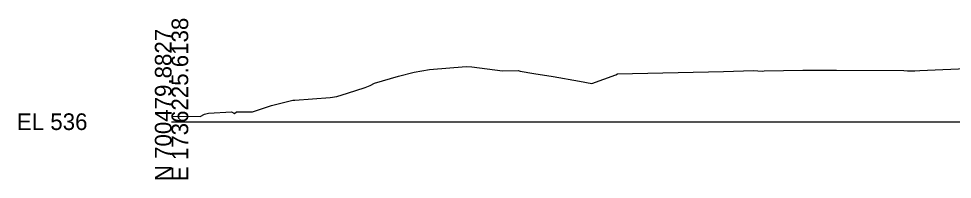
# Model space of a CAD drawing. Extents: x -26 to 803, y -10 to 646.
# Drawn here: x 474.3 to 631.2, y 190.3 to 217.3 of the extents above; entities that cross this region are included whole.
import ezdxf

# ---------------------------------------------------------------- set-up
doc = ezdxf.new("R2010")
doc.units = 0
for name, color, linetype in [('Default', 7, 'Continuous'), ('Exist Cross Section Cell', 7, 'Continuous'), ('Exist XS Ground Line', 7, 'Continuous')]:
    doc.layers.add(name, color=color, linetype=linetype)

msp = doc.modelspace()

# ---------------------------------------------------------------- linework, layer by layer
at = {"layer": 'Exist Cross Section Cell'}
msp.add_line((500, 200), (650, 200), dxfattribs=at)
at = {"layer": 'Exist XS Ground Line'}
for p, q in [((540.75, 208.33), (543.33, 208.78)), ((543.33, 208.78), (549.49, 209.28)), ((549.49, 209.28), (550.48, 209.2)), ((550.48, 209.2), (555.63, 208.56)), ((599.59, 208.53), (606.11, 208.69)), ((606.11, 208.69), (611.74, 208.64)), ((625.77, 208.61), (640.8, 209.23)), ((534.1, 206.47), (538.13, 207.66)), ((538.13, 207.66), (540.75, 208.33)), ((555.63, 208.56), (558.24, 208.58)), ((558.24, 208.58), (558.56, 208.49)), ((558.56, 208.49), (560.86, 208.09)), ((560.86, 208.09), (564.15, 207.62)), ((564.15, 207.62), (568.53, 206.82)), ((570.61, 206.42), (574.64, 207.89)), ((574.64, 207.89), (574.95, 208.03)), ((574.95, 208.03), (592.75, 208.41)), ((592.75, 208.41), (597.8, 208.59)), ((597.8, 208.59), (599.25, 208.52)), ((599.25, 208.52), (599.59, 208.53)), ((611.74, 208.64), (623.08, 208.62)), ((623.08, 208.62), (623.68, 208.55)), ((623.68, 208.55), (624.91, 208.54)), ((624.91, 208.54), (625.77, 208.61)), ((529.55, 204.8), (532.52, 205.74)), ((532.52, 205.74), (533.35, 206.1)), ((533.35, 206.1), (534.1, 206.47)), ((568.53, 206.82), (570.61, 206.42)), ((520.7, 203.64), (526.68, 204.05)), ((526.68, 204.05), (527.78, 204.21)), ((527.78, 204.21), (529.55, 204.8)), ((513.61, 201.68), (516.79, 202.7)), ((516.79, 202.7), (520.4, 203.62)), ((520.4, 203.62), (520.7, 203.64)), ((500, 200.91), (504.82, 200.88)), ((504.82, 200.88), (505.55, 201.26)), ((505.55, 201.26), (506.21, 201.43)), ((506.21, 201.43), (510.07, 201.68)), ((510.07, 201.68), (510.6, 201.35)), ((510.6, 201.35), (510.9, 201.65)), ((510.9, 201.65), (513.61, 201.68))]:
    msp.add_line(p, q, dxfattribs=at)

# ---------------------------------------------------------------- texts
at = {"layer": 'Default'}
msp.add_text('-', height=0.0001, dxfattribs=at).set_placement((500, 200))
msp.add_text('-', height=0.0001, dxfattribs=at).set_placement((500, 200))
at = {"layer": 'Exist Cross Section Cell'}
for s, p in [('E 1736225.6138', (502.8, 190)), ('N 700479.8827', (500, 190))]:
    msp.add_text(s, height=2.8, rotation=90, dxfattribs=at).set_placement(p)
msp.add_text('EL 536', height=2.8, dxfattribs=at).set_placement((474, 198.6))

doc.saveas('drawing.dxf')
